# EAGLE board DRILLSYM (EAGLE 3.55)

No outline drawn. Coordinates in mm, seen from the top.
Copper layers used: 
Holes 0.25 mm at 30.48,78.74
Holes 0.3 mm at 30.48,64.77
Holes 0.41 mm at 30.48,52.07
Holes 0.61 mm at 30.48,39.37
Holes 0.81 mm at 30.48,26.67
Holes 1.02 mm at 30.48,15.24
Holes 1.27 mm at 55.88,78.74
Holes 1.42 mm at 55.88,64.77
Holes 1.68 mm at 55.88,52.07
Holes 1.78 mm at 55.88,39.37
Holes 1.93 mm at 55.88,26.67
Holes 2.18 mm at 55.88,15.24
Holes 2.54 mm at 80.01,78.74
Holes 3.81 mm at 80.01,64.77
Holes 5.08 mm at 80.01,52.07
Holes 5.59 mm at 80.01,39.37
Holes 5.84 mm at 80.01,26.67
Holes 6.45 mm at 80.01,15.24
Holes 3.12 mm at 46.99,7.62

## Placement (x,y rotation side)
E$1  [AWING]  20.32,-19.05 0 top

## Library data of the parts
E$1 = SPECIAL

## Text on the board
Reference: 10 | 50 | 100 | 12 | 56 | 150 | 16 | 66 | 200 | 24 | 70 | 220 | 32 | 76 | 230 | 40 | 86 | 254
